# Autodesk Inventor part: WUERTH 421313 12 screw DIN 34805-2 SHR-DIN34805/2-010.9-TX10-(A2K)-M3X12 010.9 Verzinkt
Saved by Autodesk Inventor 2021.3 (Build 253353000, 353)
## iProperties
Created: 2023-03
Part Number: WUERTH 421313 12 screw DIN 34805-2 SHR-DIN34805/2-010.9-TX10-(A2K)-M3X12 010.9 Verzinkt
Material: Generic
Document SubType Name: Modeling
Designer: AdminForWorker
Density: 1 g/cm^3
Appearance: Default
Title: WUERTH 421313 12 screw DIN 34805-2 SHR-DIN34805/2-010.9-TX10-(A2K)-M3X12 010.9 Verzinkt
Author: AdminForWorker
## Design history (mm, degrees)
feature "Body1"
body "Solid1"
